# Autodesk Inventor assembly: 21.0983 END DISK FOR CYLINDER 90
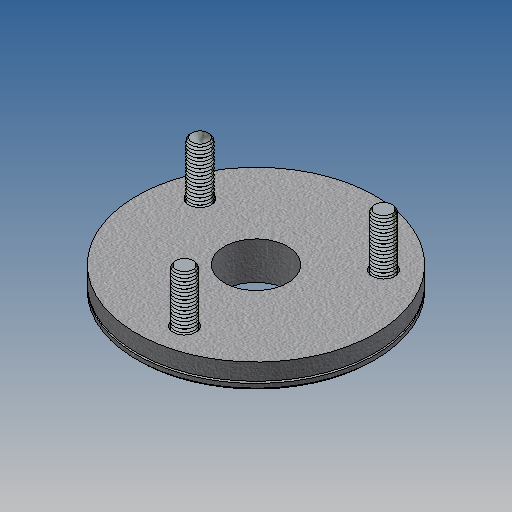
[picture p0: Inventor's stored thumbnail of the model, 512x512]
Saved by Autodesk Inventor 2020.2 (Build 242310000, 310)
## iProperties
Created: 2018-02
Part Number: 21.0983 END DISK FOR CYLINDER 90
Document SubType Name: Assembly
Designer: Admin
Author: Admin
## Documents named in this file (3)
- Y:\INVENTOR LIBRARIES\PARTS LIBRARY\BELT AND ROLLER CONVEYORS\21.0983 END DISK FOR CYLINDER 90.iam
- Y:\INVENTOR LIBRARIES\PARTS LIBRARY\BELT AND ROLLER CONVEYORS\SUBCOMPONENTS\21.0983 END DISK FOR CYLINDER PROFILE 90.ipt
- Y:\INVENTOR LIBRARIES\PARTS LIBRARY\FASTENING ELEMENTS\SUBCOMPONENTS\21.1492 POWER-LOCK SF TORX SCREW.ipt
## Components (4 placed, 2 different names)
1. 21.0983 END DISK FOR CYLINDER PROFILE 90:1 — Insert:1, Insert:2, Insert:3
2. 21.1492 POWER-LOCK SF TORX SCREW:1 — Insert:1
3. 21.1492 POWER-LOCK SF TORX SCREW:2 — Insert:2
4. 21.1492 POWER-LOCK SF TORX SCREW:3 — Insert:3
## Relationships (3: Insert 3)
- Insert:1: 21.0983 END DISK FOR CYLINDER PROFILE 90:1 ↔ 21.1492 POWER-LOCK SF TORX SCREW:1
- Insert:2: 21.0983 END DISK FOR CYLINDER PROFILE 90:1 ↔ 21.1492 POWER-LOCK SF TORX SCREW:2
- Insert:3: 21.0983 END DISK FOR CYLINDER PROFILE 90:1 ↔ 21.1492 POWER-LOCK SF TORX SCREW:3
